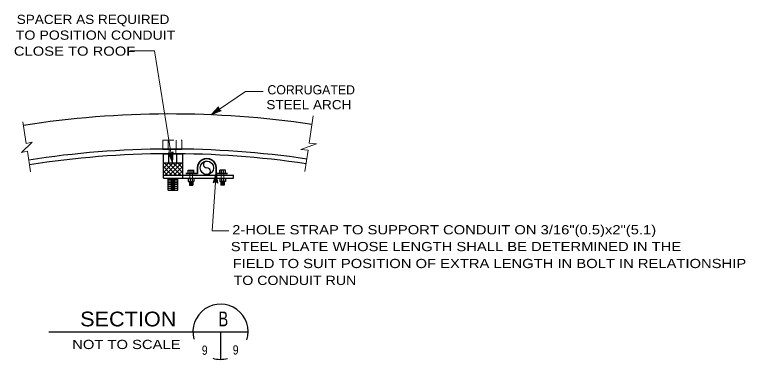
# Model space of a CAD drawing. Extents: x -39.6 to 16.1, y -17.6 to 34.
# Drawn here: x -39.55 to -29.62, y -12.61 to -7.93 of the extents above; entities that cross this region are included whole.
import ezdxf
from ezdxf.enums import TextEntityAlignment as Align

# ---------------------------------------------------------------- set-up
doc = ezdxf.new("R2010")
doc.units = 0
doc.header["$LTSCALE"] = 0.05
doc.linetypes.add('MEDIUM_DASHED', pattern=[4.5, 3, -1.5])
doc.layers.add('1', color=7, linetype='Continuous', lineweight=13)

msp = doc.modelspace()

# ---------------------------------------------------------------- linework, layer by layer
at = {"layer": '1'}
for p, q in [((-37.98821, -8.42458), (-37.65121, -8.42458)), ((-37.65121, -8.42458), (-37.40521, -9.94358)), ((-36.41721, -8.97458), (-36.88121, -9.29258)), ((-36.41721, -8.97458), (-36.17521, -8.97458)), ((-36.88121, -9.29258), (-36.78021, -9.18558)), ((-36.85021, -9.27158), (-36.78421, -9.20158)), ((-36.82121, -9.25158), (-36.78921, -9.21758)), ((-36.78921, -9.21758), (-36.78721, -9.22858)), ((-36.78721, -9.22858), (-36.77921, -9.23358)), ((-36.78421, -9.20158), (-36.78021, -9.22358)), ((-36.78021, -9.22358), (-36.76221, -9.23458)), ((-36.88121, -9.29258), (-36.74521, -9.23658)), ((-36.85021, -9.27158), (-36.76221, -9.23458)), ((-36.82121, -9.25158), (-36.77921, -9.23358)), ((-35.55121, -9.67558), (-35.49621, -9.30658)), ((-39.39421, -9.68358), (-39.44021, -9.38658)), ((-39.46021, -9.80558), (-39.31221, -9.66358)), ((-39.39421, -9.68358), (-39.31221, -9.66358)), ((-35.45221, -9.68858), (-35.66521, -9.76158)), ((-35.55121, -9.67558), (-35.45221, -9.68858)), ((-39.46021, -9.80558), (-39.37821, -9.78558)), ((-39.33521, -10.06758), (-39.37821, -9.78558)), ((-37.40521, -9.94358), (-37.45921, -9.80658)), ((-37.41121, -9.90658), (-37.44621, -9.81758)), ((-37.44621, -9.81758), (-37.42521, -9.82358)), ((-37.41721, -9.87158), (-37.43421, -9.82858)), ((-37.43421, -9.82858), (-37.42321, -9.83058)), ((-37.42521, -9.82358), (-37.40621, -9.81058)), ((-37.42321, -9.83058), (-37.41521, -9.82558)), ((-37.41721, -9.87158), (-37.41521, -9.82558)), ((-37.41121, -9.90658), (-37.40621, -9.81058)), ((-37.40521, -9.94358), (-37.39721, -9.79658)), ((-35.66521, -9.76158), (-35.56521, -9.77458)), ((-35.60921, -10.06358), (-35.56521, -9.77458)), ((-37.53021, -9.95558), (-37.51821, -9.94358)), ((-37.53021, -10.01558), (-37.50421, -9.98958)), ((-37.51621, -10.00958), (-37.53021, -9.99558)), ((-37.51621, -9.94958), (-37.52221, -9.94358)), ((-37.45621, -10.00958), (-37.51621, -9.94958)), ((-37.45621, -10.06958), (-37.51621, -10.00958)), ((-37.50421, -9.98958), (-37.45821, -9.94358)), ((-37.50421, -10.04958), (-37.44421, -9.98958)), ((-37.45621, -9.94958), (-37.46221, -9.94358)), ((-37.39621, -10.00958), (-37.45621, -9.94958)), ((-37.39621, -10.06958), (-37.45621, -10.00958)), ((-37.44421, -9.98958), (-37.39821, -9.94358)), ((-37.44421, -10.04958), (-37.38421, -9.98958)), ((-37.39621, -9.94958), (-37.40221, -9.94358)), ((-37.33621, -10.00958), (-37.39621, -9.94958)), ((-37.33621, -10.06958), (-37.39621, -10.00958)), ((-37.38421, -9.98958), (-37.33821, -9.94358)), ((-37.38421, -10.04958), (-37.32421, -9.98958)), ((-37.33621, -9.94958), (-37.34221, -9.94358)), ((-37.27621, -10.00958), (-37.33621, -9.94958)), ((-37.27621, -10.06958), (-37.33621, -10.00958)), ((-37.32421, -9.98958), (-37.27821, -9.94358)), ((-37.32421, -10.04958), (-37.26821, -9.99358)), ((-37.27621, -9.94958), (-37.28221, -9.94358)), ((-37.26821, -9.95758), (-37.27621, -9.94958)), ((-37.26821, -10.01758), (-37.27621, -10.00958)), ((-37.53021, -10.07558), (-37.50421, -10.04958)), ((-37.51621, -10.06958), (-37.53021, -10.05558)), ((-37.47421, -10.11158), (-37.51621, -10.06958)), ((-37.50621, -10.11158), (-37.50421, -10.10958)), ((-37.50421, -10.10958), (-37.44421, -10.04958)), ((-37.41421, -10.11158), (-37.45621, -10.06958)), ((-37.44621, -10.11158), (-37.44421, -10.10958)), ((-37.44421, -10.10958), (-37.38421, -10.04958)), ((-37.35421, -10.11158), (-37.39621, -10.06958)), ((-37.38621, -10.11158), (-37.38421, -10.10958)), ((-37.38421, -10.10958), (-37.32421, -10.04958)), ((-37.29421, -10.11158), (-37.33621, -10.06958)), ((-37.32621, -10.11158), (-37.32421, -10.10958)), ((-37.32421, -10.10958), (-37.26821, -10.05358)), ((-37.26821, -10.07758), (-37.27621, -10.06958)), ((-36.86621, -10.86558), (-36.81421, -10.07458)), ((-36.81421, -10.07458), (-36.85421, -10.21658)), ((-36.81621, -10.11158), (-36.84321, -10.20358)), ((-36.81621, -10.11158), (-36.80321, -10.20658)), ((-36.81421, -10.07458), (-36.79321, -10.22058)), ((-36.82221, -10.19658), (-36.84321, -10.20358)), ((-36.81921, -10.14758), (-36.83121, -10.19158)), ((-36.82121, -10.18858), (-36.83121, -10.19158)), ((-36.80321, -10.20658), (-36.82221, -10.19658)), ((-36.81221, -10.19258), (-36.82121, -10.18858)), ((-36.81921, -10.14758), (-36.81221, -10.19258)), ((-36.86621, -10.86558), (-36.64021, -10.86558))]:
    msp.add_line(p, q, dxfattribs=at)
at = {"layer": '1', "linetype": 'MEDIUM_DASHED'}
for p, q in [((-37.54021, -9.75758), (-37.54021, -9.63558)), ((-37.54021, -9.63558), (-37.27821, -9.63558)), ((-37.46621, -9.75758), (-37.46621, -9.63558)), ((-37.35621, -9.75758), (-37.35621, -9.63558)), ((-37.27821, -9.75758), (-37.27821, -9.63558)), ((-37.45221, -9.81958), (-37.45221, -9.75458)), ((-37.36021, -9.81958), (-37.36021, -9.75758)), ((-37.17021, -10.15358), (-37.17021, -10.08758)), ((-37.13621, -10.15358), (-37.13621, -10.08758)), ((-36.74421, -10.15358), (-36.74421, -10.08758)), ((-36.71021, -10.15358), (-36.71021, -10.08758))]:
    msp.add_line(p, q, dxfattribs=at)
at = {"layer": '1', "lineweight": 25}
for p, q in [((-37.54021, -9.75758), (-37.27821, -9.75758)), ((-37.53021, -10.15358), (-37.53021, -9.82158)), ((-37.53021, -9.82158), (-37.26821, -9.82158)), ((-37.45621, -9.94358), (-37.45621, -9.82158)), ((-37.34621, -9.94358), (-37.34621, -9.82158)), ((-37.26821, -10.15358), (-37.26821, -9.82158)), ((-37.53021, -9.94358), (-37.26821, -9.94358)), ((-37.53021, -10.11158), (-36.57821, -10.11158)), ((-37.16821, -10.08758), (-37.16821, -10.04358)), ((-37.14021, -10.08758), (-37.14021, -10.04358)), ((-37.11621, -10.08758), (-37.11621, -10.04358)), ((-36.76421, -10.08758), (-36.76421, -10.04358)), ((-36.74021, -10.08758), (-36.74021, -10.04358)), ((-36.71221, -10.08758), (-36.71221, -10.04358)), ((-36.57821, -10.15358), (-36.57821, -10.11158)), ((-37.53021, -10.15358), (-36.57821, -10.15358)), ((-37.46621, -10.31558), (-37.46621, -10.15358)), ((-37.46621, -10.16558), (-37.33621, -10.16558)), ((-37.46621, -10.18958), (-37.33621, -10.18958)), ((-37.46621, -10.21358), (-37.33621, -10.21358)), ((-37.42821, -10.17958), (-37.37621, -10.17958)), ((-37.42821, -10.20158), (-37.37621, -10.20158)), ((-37.42821, -10.22558), (-37.37621, -10.22558)), ((-37.33621, -10.31558), (-37.33621, -10.15358)), ((-37.17621, -10.20558), (-37.13221, -10.20558)), ((-37.17621, -10.21758), (-37.13221, -10.21758)), ((-37.16821, -10.15358), (-37.16821, -10.19758)), ((-37.14021, -10.15358), (-37.14021, -10.19758)), ((-37.13221, -10.19758), (-37.13221, -10.24758)), ((-37.11621, -10.15358), (-37.11621, -10.19758)), ((-36.76421, -10.15358), (-36.76421, -10.19758)), ((-36.74821, -10.19758), (-36.74821, -10.24758)), ((-36.70421, -10.20558), (-36.74821, -10.20558)), ((-36.70421, -10.21758), (-36.74821, -10.21758)), ((-36.74021, -10.15358), (-36.74021, -10.19758)), ((-36.71221, -10.15358), (-36.71221, -10.19758)), ((-37.46621, -10.23558), (-37.33621, -10.23558)), ((-37.46621, -10.26358), (-37.33621, -10.26358)), ((-37.46621, -10.28958), (-37.33621, -10.28958)), ((-37.46621, -10.31558), (-37.33621, -10.31558)), ((-37.42821, -10.24958), (-37.37621, -10.24958)), ((-37.42821, -10.27558), (-37.37621, -10.27558)), ((-37.42821, -10.29958), (-37.37621, -10.29958)), ((-37.17621, -10.22758), (-37.13221, -10.22758)), ((-37.17621, -10.23558), (-37.13221, -10.23558)), ((-36.70421, -10.22758), (-36.74821, -10.22758)), ((-36.70421, -10.23558), (-36.74821, -10.23558)), ((-39.08821, -12.23758), (-36.37921, -12.23758)), ((-36.75421, -12.23758), (-36.75421, -12.61258))]:
    msp.add_line(p, q, dxfattribs=at)
at = {"layer": '1', "lineweight": 35}
for p, q in [((-37.06821, -10.01358), (-37.06821, -10.08758)), ((-37.06821, -10.08758), (-37.22421, -10.08758))]:
    msp.add_line(p, q, dxfattribs=at)
at = {"layer": '1'}
for points in [[(-36.78021, -9.18558), (-36.77421, -9.21958), (-36.74521, -9.23658)], [(-37.45921, -9.80658), (-37.42621, -9.81558), (-37.39721, -9.79658)], [(-36.79321, -10.22058), (-36.82321, -10.20458), (-36.85421, -10.21658)]]:
    msp.add_lwpolyline(points, dxfattribs=at)
msp.add_lwpolyline([(-37.53021, -10.11158), (-37.53021, -9.94358), (-37.26821, -9.94358), (-37.26821, -10.11158)], close=True, dxfattribs=at)
msp.add_lwpolyline([(-37.53021, -10.11158), (-37.53021, -9.94358), (-37.26821, -9.94358), (-37.26821, -10.11158)], close=True, dxfattribs=at)
at = {"layer": '1', "lineweight": 35}
msp.add_lwpolyline([(-36.81421, -10.01358), (-36.81421, -10.08758), (-36.66021, -10.08758)], dxfattribs=at)
at = {"layer": '1', "lineweight": 25}
for points in [[(-37.19421, -10.08758), (-37.19421, -10.04358), (-37.11621, -10.04358)], [(-36.68621, -10.08758), (-36.68621, -10.04358), (-36.76421, -10.04358)], [(-37.19421, -10.15358), (-37.19421, -10.19758), (-37.11621, -10.19758)], [(-37.17621, -10.19758), (-37.17621, -10.24758), (-37.13221, -10.24758)], [(-36.68621, -10.15358), (-36.68621, -10.19758), (-36.76421, -10.19758)], [(-36.70421, -10.19758), (-36.70421, -10.24758), (-36.74821, -10.24758)]]:
    msp.add_lwpolyline(points, dxfattribs=at)
msp.add_circle((-36.94021, -10.01258), 0.091, dxfattribs=at)
for centre, radius, start, end in [((-37.42842, -22.32889), 13.04732, 81.56084, 98.8364), ((-37.42842, -22.32889), 12.57165, 81.56084, 98.8364), ((-37.42842, -22.32889), 12.50733, 81.56084, 98.8364), ((-36.75421, -12.23758), 0.375, 342.70891, 195.26862), ((-36.75421, -12.23758), 0.375, 253.4742, 284.92162)]:
    msp.add_arc(centre, radius, start, end, dxfattribs=at)
at = {"layer": '1', "lineweight": 35}
msp.add_ellipse((-36.94121, -10.01358), major_axis=(0, -0.128), ratio=0.992157, start_param=1.5707963, end_param=4.712389, dxfattribs=at)
at = {"layer": '1', "lineweight": 25}
for centre, major_axis in [((-36.93921, -9.96658), (-0.04866, 0.00108)), ((-36.94121, -10.05658), (0.04866, -0.00108))]:
    msp.add_ellipse(centre, major_axis=major_axis, ratio=0.924818, start_param=4.712389, end_param=7.8539816, dxfattribs=at)

# ---------------------------------------------------------------- texts
at = {"layer": '1'}
for s, width, p in [('SPACER AS REQUIRED', 1.1, (-39.52321, -8.05958)), ('TO POSITION CONDUIT', 1.15, (-39.53621, -8.27358)), ('CLOSE TO ROOF', 1.2, (-39.56221, -8.49058)), ('2-HOLE STRAP TO SUPPORT CONDUIT ON 3/16"(0.5)x2"(5.1)', 1.2, (-36.59621, -10.91558)), ('STEEL PLATE WHOSE LENGTH SHALL BE DETERMINED IN THE', 1.2, (-36.61521, -11.14358)), ('FIELD TO SUIT POSITION OF EXTRA LENGTH IN BOLT IN RELATIONSHIP', 1.2, (-36.59021, -11.37358)), ('TO CONDUIT RUN', 1.15, (-36.57621, -11.60258))]:
    msp.add_text(s, height=0.125, dxfattribs=dict(at, width=width)).set_placement(p)
msp.add_text('CORRUGATED', height=0.125, dxfattribs=at).set_placement((-36.11721, -9.01558))
for s, height, width, p in [('STEEL ARCH', 0.125, 1.1, (-35.55421, -9.21758)), ('SECTION', 0.2, 1.1, (-38.00821, -12.16458)), ('B', 0.2, 0.75, (-36.71671, -12.16358)), ('9', 0.125, 0.85, (-36.96921, -12.55058)), ('9', 0.125, 0.85, (-36.54921, -12.54658))]:
    msp.add_text(s, height=height, dxfattribs=dict(at, width=width)).set_placement(p, align=Align.CENTER)
at = {"layer": '1', "width": 1.2}
msp.add_text('NOT TO SCALE', height=0.125, dxfattribs=at).set_placement((-37.29821, -12.47258), align=Align.RIGHT)

doc.saveas('drawing.dxf')
